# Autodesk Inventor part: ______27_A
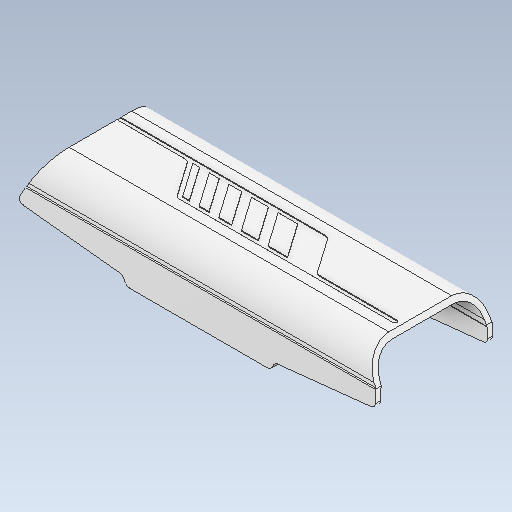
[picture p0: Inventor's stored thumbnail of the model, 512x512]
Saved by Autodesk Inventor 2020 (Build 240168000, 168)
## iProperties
Created: 2017-09
Part Number: ______27_A
Material: Générique
Document SubType Name: Modeling
Designer: bruno
Density: 1 g/cm^3
Appearance: Par défaut
Author: bruno
Sending System: SolidWorks 2016
Last Author: Prof
Last Saved: 2018-10-03
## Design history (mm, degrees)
feature "Importée1"
node "Solide1"
